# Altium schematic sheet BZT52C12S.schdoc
size 127 x 101 mm
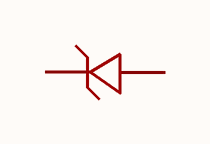
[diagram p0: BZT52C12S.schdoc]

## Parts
D?  bzt52c12s_c14643  [SOD-323_L1.8-W1.3-LS2.5-RD]  (value not drawn)

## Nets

Not connected (* = marked no-connect by the designer): D? 1(K) 2(A)

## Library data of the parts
D? = bzt52c12s_c14643: 二极管配置:1个独立式;稳压值(标称值):12V;稳压值(范围值):11.4V~12.7V;耗散功率(Pd):200mW;; Manufacturer: CJ(江苏长电/长晶); AddInBom: yes; ModelId: db63db13d9e342eb939127d413d6200b; ModelTransform: 104.3305,51.181,0,0,0,0,0,-0.004,0; Diode Configuration: 1个独立式; Zener Voltage(Nom): 12V; Reverse Leakage Current (Ir): 100nA@8V; Pd - Power Dissipation: 200mW; Impedance(Zzt): 25Ω; Impedance(Zzk): 150Ω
